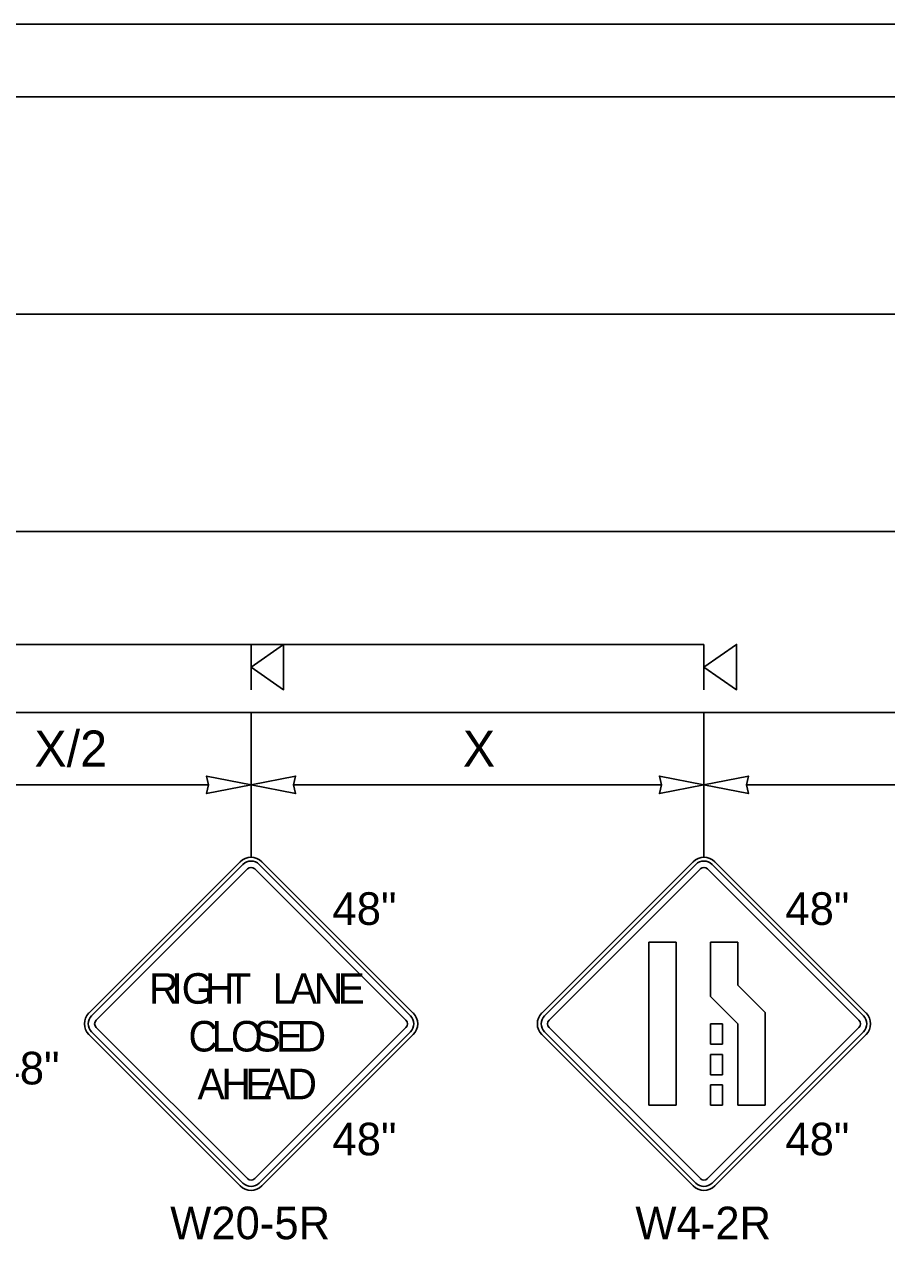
# Model space of a CAD drawing. Extents: x 99958 to 100136, y 99935 to 100013.
# Drawn here: x 100023.99 to 100025.894, y 99944.071 to 99946.756 of the extents above; entities that cross this region are included whole.
import ezdxf

# ---------------------------------------------------------------- set-up
doc = ezdxf.new("R2010")
doc.units = 0
for name, color, linetype in [('RD_ED_ShoulderPavedEdge', 7, 'Continuous'), ('RD_MK_LineEdgeWhite', 7, 'Continuous'), ('RD_MK_LineEdgeYellow', 7, 'Continuous'), ('RD_MK_LineLane', 7, 'Continuous'), ('TR_SN_ConstructionSigns', 7, 'Continuous'), ('TR_WZ_PortableSignMountBlk-Org', 7, 'Continuous'), ('TR_WZ_WorkZoneDetails', 7, 'Continuous'), ('TR_WZ_WorkZoneTextCurrent', 7, 'Continuous')]:
    doc.layers.add(name, color=color, linetype=linetype)

msp = doc.modelspace()

# ---------------------------------------------------------------- linework, layer by layer
at = {"layer": 'RD_ED_ShoulderPavedEdge'}
for p, q in [((100021.7753, 99946.7557), (100035.62, 99946.7557)), ((100021.7753, 99945.2357), (100035.62, 99945.2357))]:
    msp.add_line(p, q, dxfattribs=at)
at = {"layer": 'RD_MK_LineEdgeWhite'}
msp.add_line((100021.7753, 99945.6357), (100035.62, 99945.6357), dxfattribs=at)
at = {"layer": 'RD_MK_LineEdgeYellow'}
msp.add_line((100021.7753, 99946.5957), (100035.62, 99946.5957), dxfattribs=at)
at = {"layer": 'RD_MK_LineLane'}
msp.add_lwpolyline([(100035.62, 99946.1157), (100021.7753, 99946.1157)], dxfattribs=at)
at = {"layer": 'TR_SN_ConstructionSigns'}
for p, q in [((100024.4664, 99944.9058), (100024.1323, 99944.5717)), ((100024.4723, 99944.8999), (100024.1382, 99944.5658)), ((100024.8422, 99944.5658), (100024.5081, 99944.8999)), ((100024.8482, 99944.5717), (100024.5141, 99944.9058)), ((100025.4664, 99944.9058), (100025.1323, 99944.5717)), ((100025.4723, 99944.8999), (100025.1382, 99944.5658)), ((100025.8422, 99944.5658), (100025.5081, 99944.8999)), ((100025.8482, 99944.5717), (100025.5141, 99944.9058)), ((100024.1482, 99944.5558), (100024.4823, 99944.8899)), ((100024.4982, 99944.8899), (100024.8323, 99944.5558)), ((100025.1482, 99944.5558), (100025.4823, 99944.8899)), ((100025.4982, 99944.8899), (100025.8323, 99944.5558)), ((100025.3686, 99944.7279), (100025.4291, 99944.7279)), ((100025.3686, 99944.3679), (100025.3686, 99944.7279)), ((100025.4291, 99944.7279), (100025.3686, 99944.7279)), ((100025.3686, 99944.7279), (100025.3686, 99944.3679)), ((100025.4291, 99944.7279), (100025.4291, 99944.3679)), ((100025.4291, 99944.3679), (100025.4291, 99944.7279)), ((100025.5043, 99944.7279), (100025.5648, 99944.7279)), ((100025.5043, 99944.6083), (100025.5043, 99944.7279)), ((100025.5648, 99944.7279), (100025.5043, 99944.7279)), ((100025.5043, 99944.7279), (100025.5043, 99944.6083)), ((100025.5648, 99944.7279), (100025.5648, 99944.6334)), ((100025.5648, 99944.6334), (100025.5648, 99944.7279)), ((100025.5648, 99944.6334), (100025.6252, 99944.5729)), ((100025.6252, 99944.5729), (100025.5648, 99944.6334)), ((100025.5648, 99944.5479), (100025.5043, 99944.6083)), ((100025.5043, 99944.6083), (100025.5648, 99944.5479)), ((100025.6252, 99944.5729), (100025.6252, 99944.3679)), ((100025.6252, 99944.3679), (100025.6252, 99944.5729)), ((100024.1323, 99944.524), (100024.4664, 99944.1899)), ((100024.1382, 99944.53), (100024.4723, 99944.1959)), ((100024.4823, 99944.2058), (100024.1482, 99944.5399)), ((100024.8323, 99944.5399), (100024.4982, 99944.2058)), ((100024.5081, 99944.1959), (100024.8422, 99944.53)), ((100024.5141, 99944.1899), (100024.8482, 99944.524)), ((100025.1323, 99944.524), (100025.4664, 99944.1899)), ((100025.1382, 99944.53), (100025.4723, 99944.1959)), ((100025.4823, 99944.2058), (100025.1482, 99944.5399)), ((100025.8323, 99944.5399), (100025.4982, 99944.2058)), ((100025.5043, 99944.5479), (100025.531, 99944.5479)), ((100025.5043, 99944.5029), (100025.5043, 99944.5479)), ((100025.531, 99944.5479), (100025.5043, 99944.5479)), ((100025.5043, 99944.5479), (100025.5043, 99944.5029)), ((100025.5081, 99944.1959), (100025.8422, 99944.53)), ((100025.5141, 99944.1899), (100025.8482, 99944.524)), ((100025.531, 99944.5479), (100025.531, 99944.5029)), ((100025.531, 99944.5029), (100025.531, 99944.5479)), ((100025.5648, 99944.3679), (100025.5648, 99944.5479)), ((100025.5648, 99944.5479), (100025.5648, 99944.3679)), ((100025.531, 99944.5029), (100025.5043, 99944.5029)), ((100025.5043, 99944.5029), (100025.531, 99944.5029)), ((100025.5043, 99944.4804), (100025.531, 99944.4804)), ((100025.5043, 99944.4354), (100025.5043, 99944.4804)), ((100025.531, 99944.4804), (100025.5043, 99944.4804)), ((100025.5043, 99944.4804), (100025.5043, 99944.4354)), ((100025.531, 99944.4804), (100025.531, 99944.4354)), ((100025.531, 99944.4354), (100025.531, 99944.4804)), ((100025.531, 99944.4354), (100025.5043, 99944.4354)), ((100025.5043, 99944.4354), (100025.531, 99944.4354)), ((100025.5043, 99944.4129), (100025.531, 99944.4129)), ((100025.5043, 99944.3679), (100025.5043, 99944.4129)), ((100025.531, 99944.4129), (100025.5043, 99944.4129)), ((100025.5043, 99944.4129), (100025.5043, 99944.3679)), ((100025.531, 99944.4129), (100025.531, 99944.3679)), ((100025.531, 99944.3679), (100025.531, 99944.4129)), ((100025.4291, 99944.3679), (100025.3686, 99944.3679)), ((100025.3686, 99944.3679), (100025.4291, 99944.3679)), ((100025.531, 99944.3679), (100025.5043, 99944.3679)), ((100025.5043, 99944.3679), (100025.531, 99944.3679)), ((100025.6252, 99944.3679), (100025.5648, 99944.3679)), ((100025.5648, 99944.3679), (100025.6252, 99944.3679))]:
    msp.add_line(p, q, dxfattribs=at)
for centre, radius, start, end in [((100024.4902, 99944.882), 0.0338, 45, 135), ((100024.4902, 99944.882), 0.0253, 45, 135), ((100025.4902, 99944.882), 0.0338, 45, 135), ((100025.4902, 99944.882), 0.0253, 45, 135), ((100024.4902, 99944.882), 0.0113, 45, 135), ((100025.4902, 99944.882), 0.0113, 45, 135), ((100024.1561, 99944.5479), 0.0338, 135, 225), ((100024.1561, 99944.5479), 0.0253, 135, 225), ((100024.1561, 99944.5479), 0.0113, 135, 225), ((100024.8243, 99944.5479), 0.0113, 315, 45), ((100024.8243, 99944.5479), 0.0253, 315, 45), ((100024.8243, 99944.5479), 0.0338, 315, 45), ((100025.1561, 99944.5479), 0.0338, 135, 225), ((100025.1561, 99944.5479), 0.0253, 135, 225), ((100025.1561, 99944.5479), 0.0113, 135, 225), ((100025.8243, 99944.5479), 0.0113, 315, 45), ((100025.8243, 99944.5479), 0.0253, 315, 45), ((100025.8243, 99944.5479), 0.0338, 315, 45), ((100024.4902, 99944.2138), 0.0113, 225, 315), ((100025.4902, 99944.2138), 0.0113, 225, 315), ((100024.4902, 99944.2138), 0.0338, 225, 315), ((100024.4902, 99944.2138), 0.0253, 225, 315), ((100025.4902, 99944.2138), 0.0338, 225, 315), ((100025.4902, 99944.2138), 0.0253, 225, 315)]:
    msp.add_arc(centre, radius, start, end, dxfattribs=at)
at = {"layer": 'TR_WZ_PortableSignMountBlk-Org'}
for p, q in [((100024.4902, 99945.2858), (100024.4902, 99945.3858)), ((100025.4902, 99945.2858), (100025.4902, 99945.3858))]:
    msp.add_line(p, q, dxfattribs=at)
for points in [[(100024.4902, 99945.3357), (100024.5621, 99945.3858), (100024.5621, 99945.2858)], [(100025.4902, 99945.3357), (100025.5621, 99945.3858), (100025.5621, 99945.2858)]]:
    msp.add_lwpolyline(points, close=True, dxfattribs=at)
at = {"layer": 'TR_WZ_WorkZoneDetails'}
for p, q in [((100022.9621, 99945.3858), (100025.4902, 99945.3858)), ((100024.4902, 99945.236), (100024.4902, 99944.9157)), ((100025.4902, 99945.236), (100025.4902, 99944.9157)), ((100024.3965, 99945.0757), (100023.784, 99945.0757)), ((100025.3965, 99945.0757), (100024.584, 99945.0757)), ((100026.3965, 99945.0757), (100025.584, 99945.0757))]:
    msp.add_line(p, q, dxfattribs=at)
for points in [[(100024.4902, 99945.0757), (100024.392, 99945.095), (100024.3965, 99945.0757), (100024.392, 99945.0565)], [(100024.4902, 99945.0757), (100024.5885, 99945.095), (100024.584, 99945.0757), (100024.5885, 99945.0565)], [(100025.4902, 99945.0757), (100025.392, 99945.095), (100025.3965, 99945.0757), (100025.392, 99945.0565)], [(100025.4902, 99945.0757), (100025.5885, 99945.095), (100025.584, 99945.0757), (100025.5885, 99945.0565)]]:
    msp.add_lwpolyline(points, close=True, dxfattribs=at)

# ---------------------------------------------------------------- texts
at = {"layer": 'TR_SN_ConstructionSigns'}
for s, p in [('48"', (100024.67, 99944.7664)), ('48"', (100025.67, 99944.7664)), ('48"', (100023.926, 99944.414)), ('48"', (100024.67, 99944.2573)), ('48"', (100025.67, 99944.2573)), ('W20-5R', (100024.3116, 99944.072)), ('W4-2R', (100025.3388, 99944.072))]:
    msp.add_text(s, height=0.072, rotation=360, dxfattribs=at).set_placement(p)
for s, p in [('R', (100024.2648, 99944.5922)), ('I', (100024.3141, 99944.5922)), ('G', (100024.337, 99944.5922)), ('H', (100024.3883, 99944.5922)), ('T', (100024.4356, 99944.5922)), ('L', (100024.5375, 99944.5922)), ('A', (100024.576, 99944.5922)), ('N', (100024.6286, 99944.5922)), ('E', (100024.6813, 99944.5922)), ('C', (100024.3519, 99944.4867)), ('L', (100024.4032, 99944.4867)), ('O', (100024.4457, 99944.4867)), ('S', (100024.4956, 99944.4867)), ('E', (100024.5449, 99944.4867)), ('D', (100024.5908, 99944.4867)), ('A', (100024.3721, 99944.3812)), ('H', (100024.4248, 99944.3812)), ('E', (100024.4774, 99944.3812)), ('A', (100024.5179, 99944.3812)), ('D', (100024.5706, 99944.3812))]:
    msp.add_text(s, height=0.0675, dxfattribs=at).set_placement(p)
at = {"layer": 'TR_WZ_WorkZoneTextCurrent'}
for s, p in [('X/2', (100024.0117, 99945.1157)), ('X', (100024.9578, 99945.1157))]:
    msp.add_text(s, height=0.08, rotation=360, dxfattribs=at).set_placement(p)

doc.saveas('drawing.dxf')
